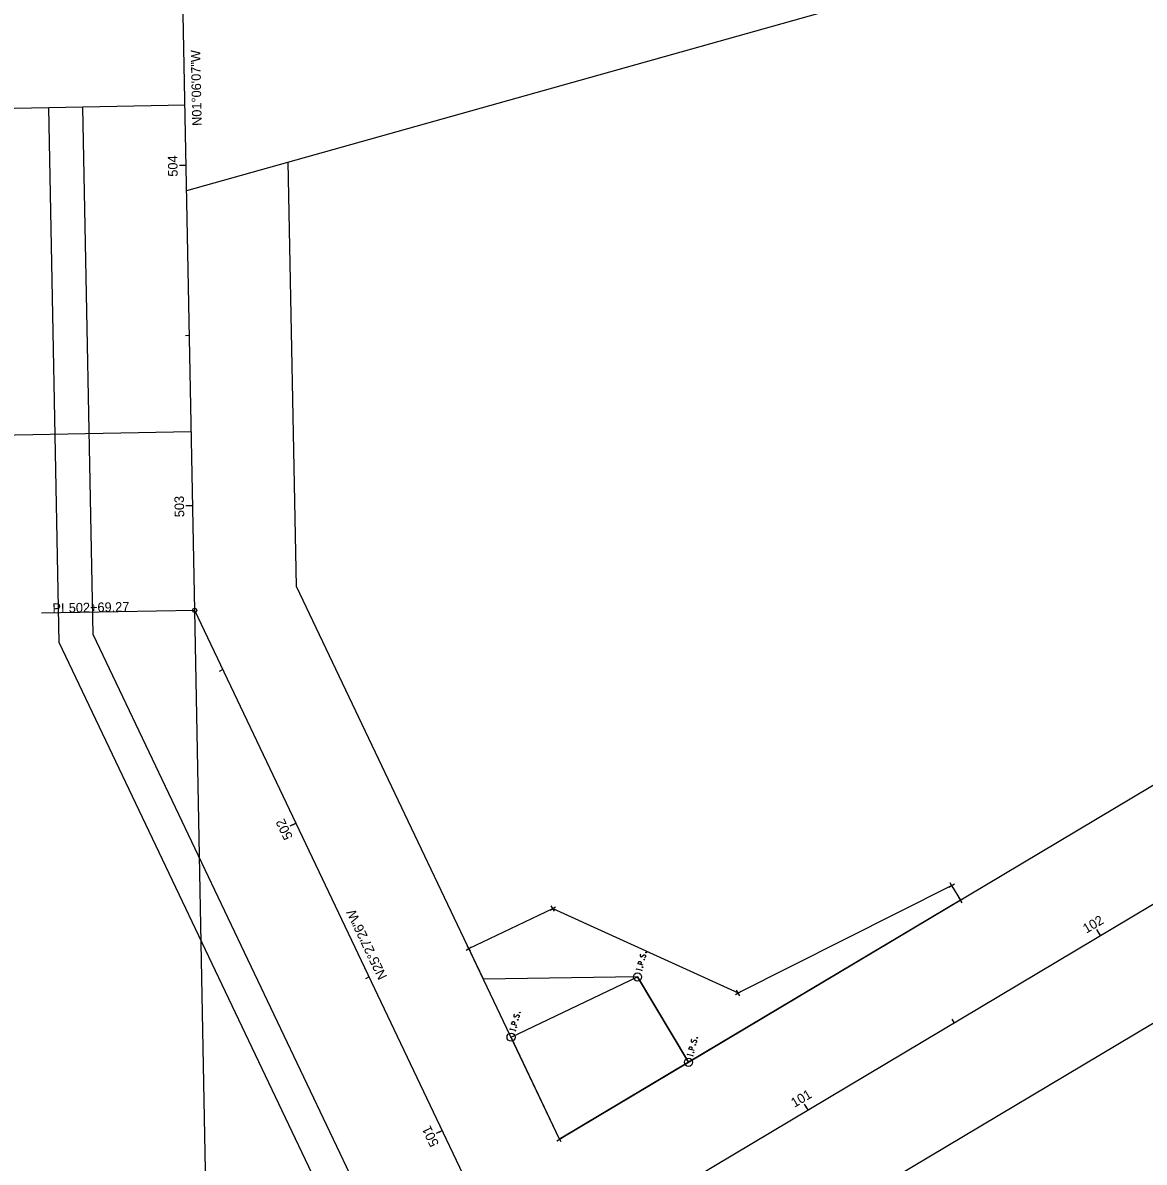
# Model space of a CAD drawing. Extents: x 2351593 to 2354159, y 766293 to 768001.
# Drawn here: x 2352271.1 to 2352600.5, y 766966.8 to 767301.5 of the extents above; entities that cross this region are included whole.
import ezdxf

# ---------------------------------------------------------------- set-up
doc = ezdxf.new("R2010")
doc.units = 0
for name, color, linetype in [('BD_X_Building', 7, 'Continuous'), ('PV_X_COP', 7, 'Continuous'), ('PV_X_Curb', 7, 'Continuous'), ('PV_X_Driveway', 7, 'Continuous'), ('PV_X_Steps', 7, 'Continuous'), ('PV_X_Walk', 7, 'Continuous'), ('RD_X_Fence', 7, 'Continuous'), ('RD_X_Misc_Items', 7, 'Continuous'), ('SV_P_Mon_Cells_Set', 7, 'Continuous'), ('SV_X_Break_Lines', 7, 'Continuous'), ('SV_X_Mon_Cells_Found', 7, 'Continuous'), ('SV_X_Random_Point', 7, 'Continuous'), ('SV_X_Shot_Marker', 7, 'Continuous'), ('UT_X_Water_Cells', 7, 'Continuous'), ('VG_X_Cells', 7, 'Continuous'), ('VG_X_Flower_Bed', 7, 'Continuous'), ('VG_X_Shrub_Line_Lt', 7, 'Continuous')]:
    doc.layers.add(name, color=color, linetype=linetype)

msp = doc.modelspace()

# ---------------------------------------------------------------- linework, layer by layer
at = {"layer": 'BD_X_Building'}
for p, q in [((2352543.1, 767047.58), (2352544.72, 767048.55)), ((2352544.39, 767047.26), (2352543.43, 767048.88)), ((2352545.66, 767043.29), (2352547.28, 767044.26)), ((2352546.96, 767042.96), (2352545.99, 767044.58)), ((2352425.96, 767040.82), (2352427.58, 767041.79)), ((2352427.25, 767040.5), (2352426.28, 767042.12)), ((2352401.3, 767029.09), (2352402.93, 767030.06)), ((2352402.6, 767028.77), (2352401.63, 767030.39)), ((2352480.43, 767016.01), (2352482.05, 767016.97)), ((2352481.72, 767015.68), (2352480.75, 767017.3)), ((2352427.97, 766973.06), (2352429.59, 766974.03)), ((2352429.27, 766972.74), (2352428.3, 766974.36))]:
    msp.add_line(p, q, dxfattribs=at)
at = {"layer": 'PV_X_COP'}
for p, q in [((2352319.24, 767252.27), (2352591.72, 767328.7)), ((2352318.76, 767277.31), (2352107.01, 767273.24)), ((2352320.6, 767181.33), (2352109.81, 767177.28))]:
    msp.add_line(p, q, dxfattribs=at)
at = {"layer": 'PV_X_Curb'}
msp.add_line((2352337.69, 766292.88), (2352321.61, 767128.88), dxfattribs=at)
at = {"layer": 'PV_X_Walk'}
msp.add_line((2352321.61, 767128.88), (2352276.62, 767128.01), dxfattribs=at)
msp.add_circle((2352321.61, 767128.88), 0.6, dxfattribs=at)
at = {"layer": 'RD_X_Fence'}
for p, q in [((2352414.52, 767003.5), (2352451.66, 767021.18)), ((2352451.66, 767021.18), (2352466.61, 766996.12)), ((2352428.78, 766973.55), (2352414.52, 767003.5)), ((2352466.61, 766996.12), (2352428.78, 766973.55))]:
    msp.add_line(p, q, dxfattribs=at)
at = {"layer": 'RD_X_Misc_Items'}
for p, q in [((2352428.78, 766973.55), (2354128.21, 767987.61)), ((2352450.22, 766916.47), (2354158.95, 767936.09)), ((2352291.74, 767121.83), (2352288.76, 767276.74)), ((2352351.48, 767135.93), (2352349.08, 767260.64)), ((2352428.78, 766973.55), (2352351.48, 767135.93)), ((2352377.03, 766942.67), (2352291.74, 767121.83))]:
    msp.add_line(p, q, dxfattribs=at)
at = {"layer": 'SV_P_Mon_Cells_Set'}
for p, q in [((2352319.1, 767259.59), (2352317.1, 767259.55)), ((2352320.06, 767209.6), (2352318.86, 767209.57)), ((2352321.02, 767159.6), (2352319.02, 767159.57)), ((2352329.89, 767111.48), (2352328.81, 767110.97)), ((2352351.38, 767066.34), (2352349.58, 767065.48)), ((2352587.61, 767033.38), (2352586.58, 767035.1)), ((2352372.88, 767021.19), (2352371.79, 767020.67)), ((2352544.67, 767007.76), (2352544.06, 767008.79)), ((2352501.73, 766982.14), (2352500.71, 766983.86)), ((2352394.37, 766976.05), (2352392.56, 766975.19))]:
    msp.add_line(p, q, dxfattribs=at)
at = {"layer": 'SV_X_Break_Lines'}
msp.add_line((2352321.61, 767128.88), (2352276.62, 767128.01), dxfattribs=at)
msp.add_circle((2352321.61, 767128.88), 0.6, dxfattribs=at)
at = {"layer": 'SV_X_Mon_Cells_Found'}
for p, q in [((2351616.47, 766453.89), (2354143.58, 767961.85)), ((2352321.61, 767128.88), (2352315.68, 767437.12)), ((2352415.86, 766930.9), (2352321.61, 767128.88))]:
    msp.add_line(p, q, dxfattribs=at)
at = {"layer": 'SV_X_Random_Point'}
for p, q in [((2352481.24, 767016.49), (2352543.91, 767048.07)), ((2352543.91, 767048.07), (2352546.47, 767043.77)), ((2352402.11, 767029.57), (2352426.76, 767041.31)), ((2352426.76, 767041.31), (2352481.24, 767016.49))]:
    msp.add_line(p, q, dxfattribs=at)
at = {"layer": 'SV_X_Shot_Marker'}
for p, q in [((2352319.1, 767259.59), (2352317.9, 767259.56)), ((2352321.02, 767159.6), (2352319.82, 767159.58)), ((2352351.38, 767066.34), (2352350.3, 767065.82)), ((2352587.61, 767033.38), (2352586.99, 767034.41)), ((2352501.73, 766982.14), (2352501.12, 766983.17)), ((2352394.37, 766976.05), (2352393.28, 766975.53))]:
    msp.add_line(p, q, dxfattribs=at)
at = {"layer": 'UT_X_Water_Cells'}
for p, q in [((2352281.78, 767119.48), (2352278.76, 767276.54)), ((2352368.41, 766937.52), (2352281.78, 767119.48))]:
    msp.add_line(p, q, dxfattribs=at)
at = {"layer": 'VG_X_Cells'}
for p, q in [((2352414.52, 767003.5), (2352451.66, 767021.18)), ((2352451.66, 767021.18), (2352466.61, 766996.12))]:
    msp.add_line(p, q, dxfattribs=at)
at = {"layer": 'VG_X_Flower_Bed'}
for p, q in [((2352481.24, 767016.49), (2352543.91, 767048.07)), ((2352543.91, 767048.07), (2352546.47, 767043.77)), ((2352546.47, 767043.77), (2352466.61, 766996.12)), ((2352402.11, 767029.58), (2352426.77, 767041.31)), ((2352426.77, 767041.31), (2352481.24, 767016.49)), ((2352406.41, 767020.54), (2352402.11, 767029.58)), ((2352451.66, 767021.18), (2352406.41, 767020.54)), ((2352466.61, 766996.12), (2352451.66, 767021.18))]:
    msp.add_line(p, q, dxfattribs=at)
at = {"layer": 'VG_X_Shrub_Line_Lt'}
for points in [[(2352452.65, 767027.91), (2352452.62, 767027.89), (2352452.59, 767027.87), (2352452.52, 767027.78), (2352452.47, 767027.67), (2352452.45, 767027.58), (2352452.44, 767027.55), (2352452.44, 767027.4), (2352452.49, 767027.27), (2352452.57, 767027.17), (2352452.66, 767027.12), (2352452.73, 767027.1), (2352452.83, 767027.1), (2352452.94, 767027.16), (2352453.46, 767027.66), (2352453.52, 767027.7), (2352453.57, 767027.71), (2352453.65, 767027.71), (2352453.72, 767027.69), (2352453.79, 767027.66), (2352453.84, 767027.64), (2352453.9, 767027.6), (2352453.94, 767027.57), (2352453.97, 767027.54), (2352454, 767027.5), (2352454.02, 767027.46), (2352454.03, 767027.41), (2352454.03, 767027.38), (2352454.02, 767027.28), (2352453.98, 767027.13), (2352453.94, 767027.04), (2352453.81, 767026.92), (2352453.72, 767026.85)], [(2352453.55, 767026.27), (2352453.56, 767026.33), (2352453.59, 767026.35), (2352453.65, 767026.37), (2352453.71, 767026.36), (2352453.75, 767026.31), (2352453.77, 767026.27), (2352453.75, 767026.22), (2352453.72, 767026.19), (2352453.67, 767026.17), (2352453.6, 767026.19), (2352453.56, 767026.23), (2352453.55, 767026.27)], [(2352454.08, 767028.39), (2352454.1, 767028.44), (2352454.13, 767028.47), (2352454.18, 767028.49), (2352454.25, 767028.47), (2352454.29, 767028.43), (2352454.3, 767028.39), (2352454.29, 767028.34), (2352454.26, 767028.31), (2352454.2, 767028.29), (2352454.14, 767028.31), (2352454.1, 767028.35), (2352454.08, 767028.39)], [(2352451.37, 767023.33), (2352451.46, 767023.67)], [(2352452.97, 767023.11), (2352451.42, 767023.5)], [(2352453.35, 767024.63), (2352451.8, 767025.02), (2352451.93, 767025.53), (2352451.96, 767025.58), (2352452, 767025.65), (2352452.03, 767025.68), (2352452.07, 767025.7), (2352452.14, 767025.73), (2352452.21, 767025.75), (2352452.31, 767025.74), (2352452.46, 767025.71), (2352452.5, 767025.68), (2352452.57, 767025.64), (2352452.64, 767025.58), (2352452.67, 767025.53), (2352452.69, 767025.49), (2352452.7, 767025.43), (2352452.69, 767025.34), (2352452.56, 767024.83)], [(2352452.93, 767022.94), (2352453.01, 767023.28)], [(2352453, 767024.09), (2352453.01, 767024.14), (2352453.04, 767024.17), (2352453.1, 767024.19), (2352453.16, 767024.17), (2352453.2, 767024.13), (2352453.22, 767024.09), (2352453.2, 767024.04), (2352453.17, 767024.01), (2352453.11, 767023.99), (2352453.05, 767024.01), (2352453.01, 767024.05), (2352453, 767024.09)], [(2352415.51, 767010.23), (2352415.48, 767010.22), (2352415.45, 767010.19), (2352415.39, 767010.1), (2352415.34, 767009.99), (2352415.32, 767009.91), (2352415.31, 767009.88), (2352415.31, 767009.73), (2352415.35, 767009.59), (2352415.43, 767009.49), (2352415.52, 767009.45), (2352415.6, 767009.43), (2352415.7, 767009.42), (2352415.81, 767009.49), (2352416.32, 767009.98), (2352416.38, 767010.02), (2352416.44, 767010.03), (2352416.52, 767010.04), (2352416.59, 767010.02), (2352416.66, 767009.99), (2352416.71, 767009.97), (2352416.76, 767009.93), (2352416.81, 767009.89), (2352416.84, 767009.86), (2352416.87, 767009.82), (2352416.88, 767009.78), (2352416.9, 767009.74), (2352416.9, 767009.7), (2352416.89, 767009.6), (2352416.85, 767009.45), (2352416.8, 767009.36), (2352416.68, 767009.24), (2352416.59, 767009.18)], [(2352416.95, 767010.71), (2352416.96, 767010.77), (2352416.99, 767010.79), (2352417.05, 767010.81), (2352417.11, 767010.8), (2352417.15, 767010.75), (2352417.17, 767010.71), (2352417.16, 767010.66), (2352417.12, 767010.63), (2352417.07, 767010.61), (2352417, 767010.63), (2352416.96, 767010.67), (2352416.95, 767010.71)], [(2352414.24, 767005.65), (2352414.33, 767006)], [(2352416.22, 767006.95), (2352414.67, 767007.34), (2352414.8, 767007.86), (2352414.82, 767007.91), (2352414.87, 767007.97), (2352414.9, 767008), (2352414.93, 767008.03), (2352415, 767008.05), (2352415.07, 767008.07), (2352415.18, 767008.07), (2352415.32, 767008.03), (2352415.37, 767008.01), (2352415.44, 767007.97), (2352415.51, 767007.9), (2352415.54, 767007.85), (2352415.55, 767007.81), (2352415.56, 767007.75), (2352415.55, 767007.66), (2352415.42, 767007.15)], [(2352415.86, 767006.42), (2352415.88, 767006.47), (2352415.91, 767006.5), (2352415.97, 767006.51), (2352416.03, 767006.5), (2352416.07, 767006.45), (2352416.08, 767006.42), (2352416.07, 767006.36), (2352416.04, 767006.34), (2352415.98, 767006.32), (2352415.92, 767006.33), (2352415.88, 767006.38), (2352415.86, 767006.42)], [(2352416.41, 767008.6), (2352416.43, 767008.65), (2352416.46, 767008.68), (2352416.52, 767008.69), (2352416.58, 767008.68), (2352416.62, 767008.64), (2352416.63, 767008.6), (2352416.62, 767008.54), (2352416.59, 767008.52), (2352416.53, 767008.5), (2352416.47, 767008.51), (2352416.43, 767008.56), (2352416.41, 767008.6)], [(2352415.84, 767005.43), (2352414.28, 767005.83)], [(2352415.79, 767005.26), (2352415.88, 767005.6)], [(2352467.6, 767002.85), (2352467.57, 767002.84), (2352467.54, 767002.81), (2352467.48, 767002.72), (2352467.42, 767002.61), (2352467.4, 767002.53), (2352467.39, 767002.49), (2352467.4, 767002.35), (2352467.44, 767002.21), (2352467.52, 767002.11), (2352467.61, 767002.06), (2352467.68, 767002.05), (2352467.79, 767002.04), (2352467.89, 767002.11), (2352468.41, 767002.6), (2352468.47, 767002.64), (2352468.52, 767002.65), (2352468.6, 767002.65), (2352468.68, 767002.64), (2352468.75, 767002.61), (2352468.79, 767002.58), (2352468.85, 767002.55), (2352468.89, 767002.51), (2352468.92, 767002.48), (2352468.95, 767002.44), (2352468.97, 767002.4), (2352468.98, 767002.35), (2352468.99, 767002.32), (2352468.97, 767002.22), (2352468.94, 767002.07), (2352468.89, 767001.98), (2352468.77, 767001.86), (2352468.67, 767001.8)], [(2352469.03, 767003.33), (2352469.05, 767003.38), (2352469.08, 767003.41), (2352469.14, 767003.43), (2352469.2, 767003.41), (2352469.24, 767003.37), (2352469.26, 767003.33), (2352469.24, 767003.28), (2352469.21, 767003.25), (2352469.15, 767003.23), (2352469.09, 767003.25), (2352469.05, 767003.29), (2352469.03, 767003.33)], [(2352468.3, 766999.57), (2352466.75, 766999.96), (2352466.88, 767000.47), (2352466.91, 767000.52), (2352466.95, 767000.59), (2352466.98, 767000.62), (2352467.02, 767000.64), (2352467.09, 767000.67), (2352467.16, 767000.69), (2352467.26, 767000.69), (2352467.41, 767000.65), (2352467.45, 767000.62), (2352467.52, 767000.59), (2352467.6, 767000.52), (2352467.62, 767000.47), (2352467.64, 767000.43), (2352467.65, 767000.37), (2352467.64, 767000.28), (2352467.51, 766999.77)], [(2352468.5, 767001.21), (2352468.51, 767001.27), (2352468.55, 767001.29), (2352468.6, 767001.31), (2352468.66, 767001.3), (2352468.7, 767001.25), (2352468.72, 767001.21), (2352468.71, 767001.16), (2352468.67, 767001.14), (2352468.62, 767001.12), (2352468.56, 767001.13), (2352468.52, 767001.18), (2352468.5, 767001.21)], [(2352466.33, 766998.27), (2352466.41, 766998.61)], [(2352467.92, 766998.05), (2352466.37, 766998.44)], [(2352467.88, 766997.88), (2352467.96, 766998.22)], [(2352467.95, 766999.03), (2352467.96, 766999.09), (2352467.99, 766999.11), (2352468.05, 766999.13), (2352468.11, 766999.12), (2352468.15, 766999.07), (2352468.17, 766999.03), (2352468.16, 766998.98), (2352468.12, 766998.96), (2352468.07, 766998.94), (2352468.01, 766998.95), (2352467.97, 766999), (2352467.95, 766999.03)]]:
    msp.add_lwpolyline(points, dxfattribs=at)
for centre in [(2352451.66, 767021.18), (2352414.52, 767003.5), (2352466.61, 766996.12)]:
    msp.add_circle(centre, 1.2, dxfattribs=at)

# ---------------------------------------------------------------- texts
at = {"layer": 'PV_X_Driveway'}
for s, rotation, p in [('N01°06\'07"W', 91.1019, (2352323.67, 767271.23)), ('N25°27\'26"W', 115.4572, (2352378.17, 767021.24))]:
    msp.add_text(s, height=2.8, rotation=rotation, dxfattribs=at).set_placement(p)
at = {"layer": 'PV_X_Steps'}
for s, rotation, p in [('N01°06\'07"W', 91.1019, (2352323.67, 767271.23)), ('N25°27\'26"W', 115.4572, (2352378.17, 767021.24))]:
    msp.add_text(s, height=2.8, rotation=rotation, dxfattribs=at).set_placement(p)
at = {"layer": 'PV_X_Walk'}
for s, p in [('PI', (2352279.85, 767128.12)), ('502+69.27', (2352284.63, 767128.22))]:
    msp.add_text(s, height=2.8, rotation=1.1019, dxfattribs=at).set_placement(p)
at = {"layer": 'SV_P_Mon_Cells_Set'}
for s, rotation, p in [('504', 91.1019, (2352316.61, 767256.3)), ('503', 91.1019, (2352318.54, 767156.29)), ('502', 115.4572, (2352350.49, 767062.29)), ('102', 30.825, (2352583.49, 767033.89)), ('101', 30.825, (2352497.76, 766982.73)), ('501', 115.4572, (2352393.41, 766972.14))]:
    msp.add_text(s, height=2.8, rotation=rotation, dxfattribs=at).set_placement(p)
at = {"layer": 'SV_X_Break_Lines'}
for s, p in [('PI', (2352279.85, 767128.12)), ('502+69.27', (2352284.63, 767128.22))]:
    msp.add_text(s, height=2.8, rotation=1.1019, dxfattribs=at).set_placement(p)

doc.saveas('drawing.dxf')
